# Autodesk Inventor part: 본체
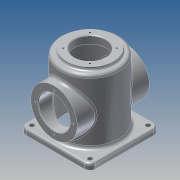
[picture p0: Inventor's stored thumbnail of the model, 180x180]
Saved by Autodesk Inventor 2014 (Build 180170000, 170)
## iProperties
Created: 2015-10
Part Number: 본체
Material: 알루미늄 6061
Document SubType Name: Modeling
Designer: 시험용
Density: 2.71 g/cm^3
Appearance: 알루미늄 - 평지
Mass: 985.996 g
Surface Area: 1037.38 cm^2
Volume: 363.836 cm^3
Author: 시험용
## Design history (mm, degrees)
sketch "스케치1"
  geometry: L1 (-50, 60)-(50, 60); L2 (60, 50)-(60, -50); L3 (50, -60)-(-50, -60); L4 (-60, -50)-(-60, 50); C1 r 4 at (-50, 50); C2 r 4 at (-50, -50); C3 r 4 at (50, -50); C4 r 4 at (50, 50); A1 r 10 centre (-50, 50) between (-50, 60) and (-60, 50); A2 r 10 centre (50, 50) between (60, 50) and (50, 60); A3 r 10 centre (50, -50) between (50, -60) and (60, -50); A4 r 10 centre (-50, -50) between (-60, -50) and (-50, -60); 6 further points
  constraints: 8 centre point, 8 end point, 8 point on circle, 8 tangent, 6 equal radius, 6 point on line, 4 coincident, 2 midpoint, 2 parallel, 1 horizontal, 1 horizontal alignment, 1 perpendicular, 1 vertical alignment
  dimensions: "d0" = 120 distance of point (-60, 60) point (60, 60); "d1" = 120 distance of point (60, 60) point (60, -60); "d2" = 10 radius of A1; "d3" = 8 diameter of C2
extrude "돌출1" new body sketch "스케치1" distance "d4" = 10; taper "d5" = 0 deg
sketch "스케치2"
  geometry: C1 r 50 at (0, 0); 1 further point
  constraints: 1 centre point, 1 coincident
  dimensions: "d6" = 100 diameter of C1
extrude "돌출2" join sketch "스케치2" distance "d7" = 110; taper "d8" = 0 deg
sketch "스케치4"
  geometry: C1 r 45 at (0, 0); 1 further point
  constraints: 1 centre point, 1 coincident
  dimensions: "d12" = 90 diameter of C1
extrude "돌출4" cut sketch "스케치4" distance "d13" = 112; taper "d14" = 0 deg
sketch "스케치3"
  geometry: C1 r 40 at (0, 0); 1 further point
  constraints: 1 centre point, 1 coincident
  dimensions: "d9" = 80 diameter of C1
extrude "돌출3" join sketch "스케치3" distance "d10" = 5; taper "d11" = 0 deg
sketch "스케치5"
  geometry: C1 r 27 at (0, 0); 1 further point
  constraints: 1 centre point, 1 coincident
  dimensions: "d15" = 54 diameter of C1
extrude "돌출5" cut sketch "스케치5" stored distance "d16" = 112; taper "d17" = 0 deg
fillet "모깎기1" dims "d18" = 3
fillet "모깎기2" dims "d19" = 5
fillet "모깎기3" dims "d20" = 5
fillet "모깎기4" dims "d21" = 3
chamfer "모따기1" distance "d22" = 1; stored, may be unused: second distance "d23" = 2, angle "d24" = 45 deg
chamfer "모따기2" distance "d25" = 3; stored, may be unused: second distance "d26" = 2, angle "d27" = 45 deg
sketch "스케치6"
  geometry: L1 (0, 0)-(0, 32.5); L2 (0, 0)-(22.981, 22.981); A1 r 32.5 centre (0, 0) between (22.981, 22.981) and (0, 32.5); 4 further points
  constraints: 4 end point, 2 point on circle, 1 centre point, 1 coincident, 1 vertical, 5 other
  dimensions: "d28" = 65 diameter of A1; "d29" = 45 deg angle of L2 L1; "d32" = 360 deg dimension on point (0, 0) L2.end (derived)
hole "구멍1" sketch "스케치6" at (22.981, 22.981), (-22.981, 22.981), (-22.981, -22.981), (22.981, -22.981) diameter "d34" = 3.242; stored, may be unused: countersink angle "d38" = 90 deg, drill point angle "d40" = 118 deg; dims "d35" = 8, "d36" = 4, "d37" = 2, "d39" = 10
node "작업 평면2"
sketch "스케치7"
  geometry: L1 (50, -10)-(-50, -10) reference; C1 r 40 at (0, 50); 1 further point
  constraints: 1 centre point
  dimensions: "d42" = 60 distance from line of C1.centre L1; "d43" = 80 diameter of C1
extrude "돌출6" join sketch "스케치7" stored distance "d44" = 112; taper "d45" = 0 deg
fillet "모깎기5" dims "d46" = 5
sketch "스케치8"
  geometry: C1 r 40 at (0, 0) reference; A1 r 32.5 centre (0, 0) between (0, 32.5) and (-32.5, 0); 3 further points
  constraints: 4 point on circle, 2 horizontal alignment, 2 vertical alignment, 1 centre point, 1 coincident
  dimensions: "d47" = 65 diameter of A1
hole "구멍2" sketch "스케치8" at (0, 32.5), (-32.5, 0), (0, -32.5), (32.5, 0) diameter "d48" = 3.242; stored, may be unused: countersink angle "d52" = 90 deg, drill point angle "d54" = 118 deg; dims "d49" = 8, "d50" = 4, "d51" = 2, "d53" = 10
sketch "스케치9"
  geometry: C1 r 40 at (0, 0) reference; C2 r 27 at (0, 0); 1 further point
  constraints: 1 centre point, 1 coincident
  dimensions: "d55" = 54 diameter of C2
extrude "돌출7" cut sketch "스케치9" stored distance "d56" = 0; taper "d57" = 0 deg
chamfer "모따기3" distance "d58" = 1; stored, may be unused: second distance "d59" = 2, angle "d60" = 45 deg
fillet "모깎기6" dims "d61" = 3
node "작업 평면5"
sketch "스케치11"
  geometry: L1 (-5, 35)-(-5, 85); L2 (-5, 85)-(5, 85); L3 (5, 85)-(5, 35); L4 (5, 35)-(-5, 35); L5 (50, -10)-(-50, -10) reference; L6 (-5, 60)-(5, 60); 3 further points
  constraints: 4 midpoint, 2 end point, 1 vertical alignment, 2 other
  dimensions: "d66" = 70 distance between parallel lines of L5 L6; "d67" = 10 distance of L1.end L2.end; "d68" = 50 distance of L2.end L3.end
feature "엠보싱1" sketch "스케치11" dims "d0" = 120, "d1" = 120, "d2" = 10, "d3" = 8, "d8" = 0, "d69" = 0.5, "d70" = 0
node "솔리드1"
mirror "대칭1"
